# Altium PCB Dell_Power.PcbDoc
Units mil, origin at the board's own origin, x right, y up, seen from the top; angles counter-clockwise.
Board outline 2900 x 3225 mil, 2 copper layers (Top Layer, Bottom Layer); 31 components, 23 nets, 178 pads, 103 vias.
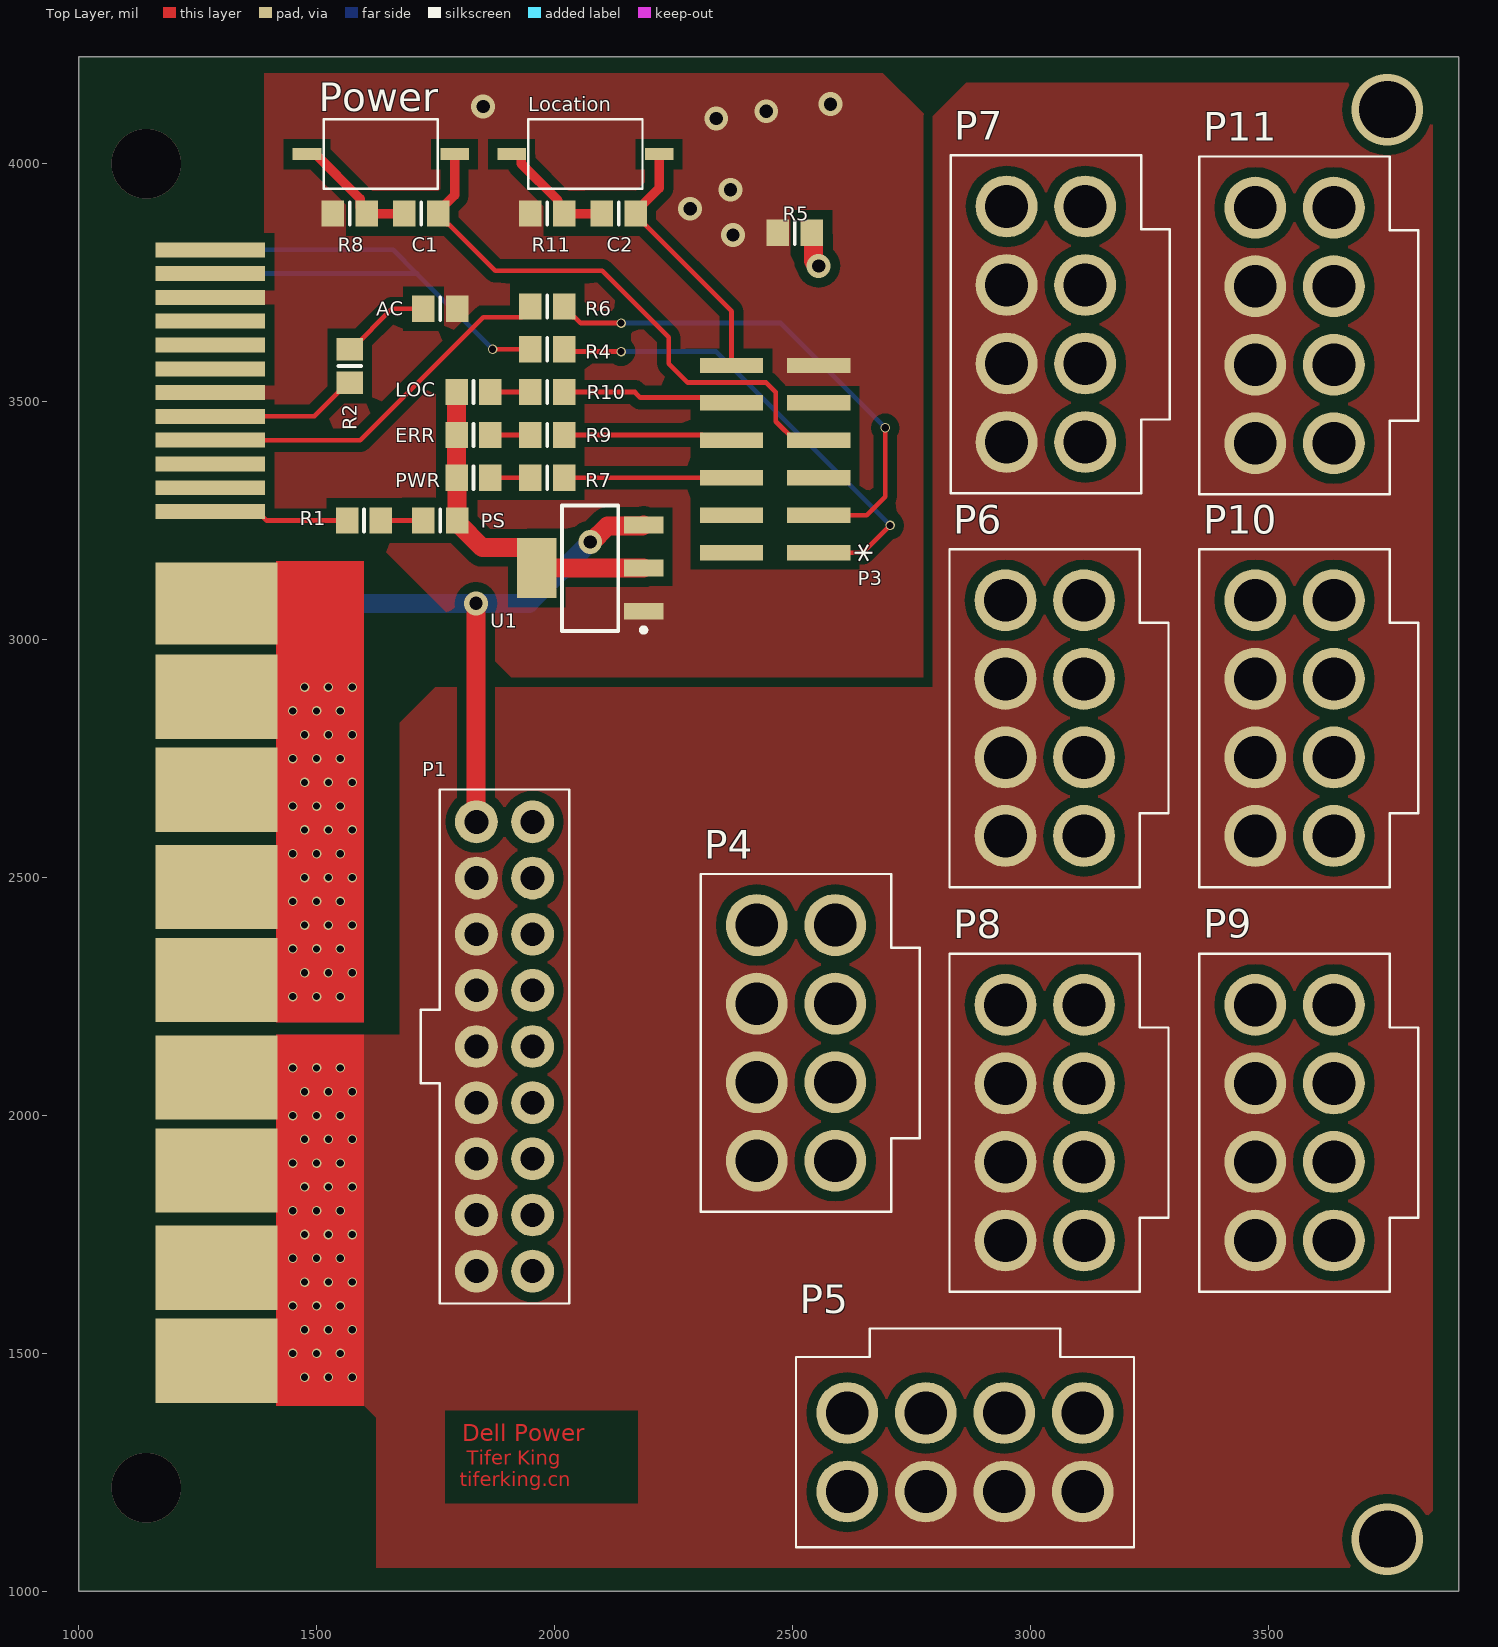
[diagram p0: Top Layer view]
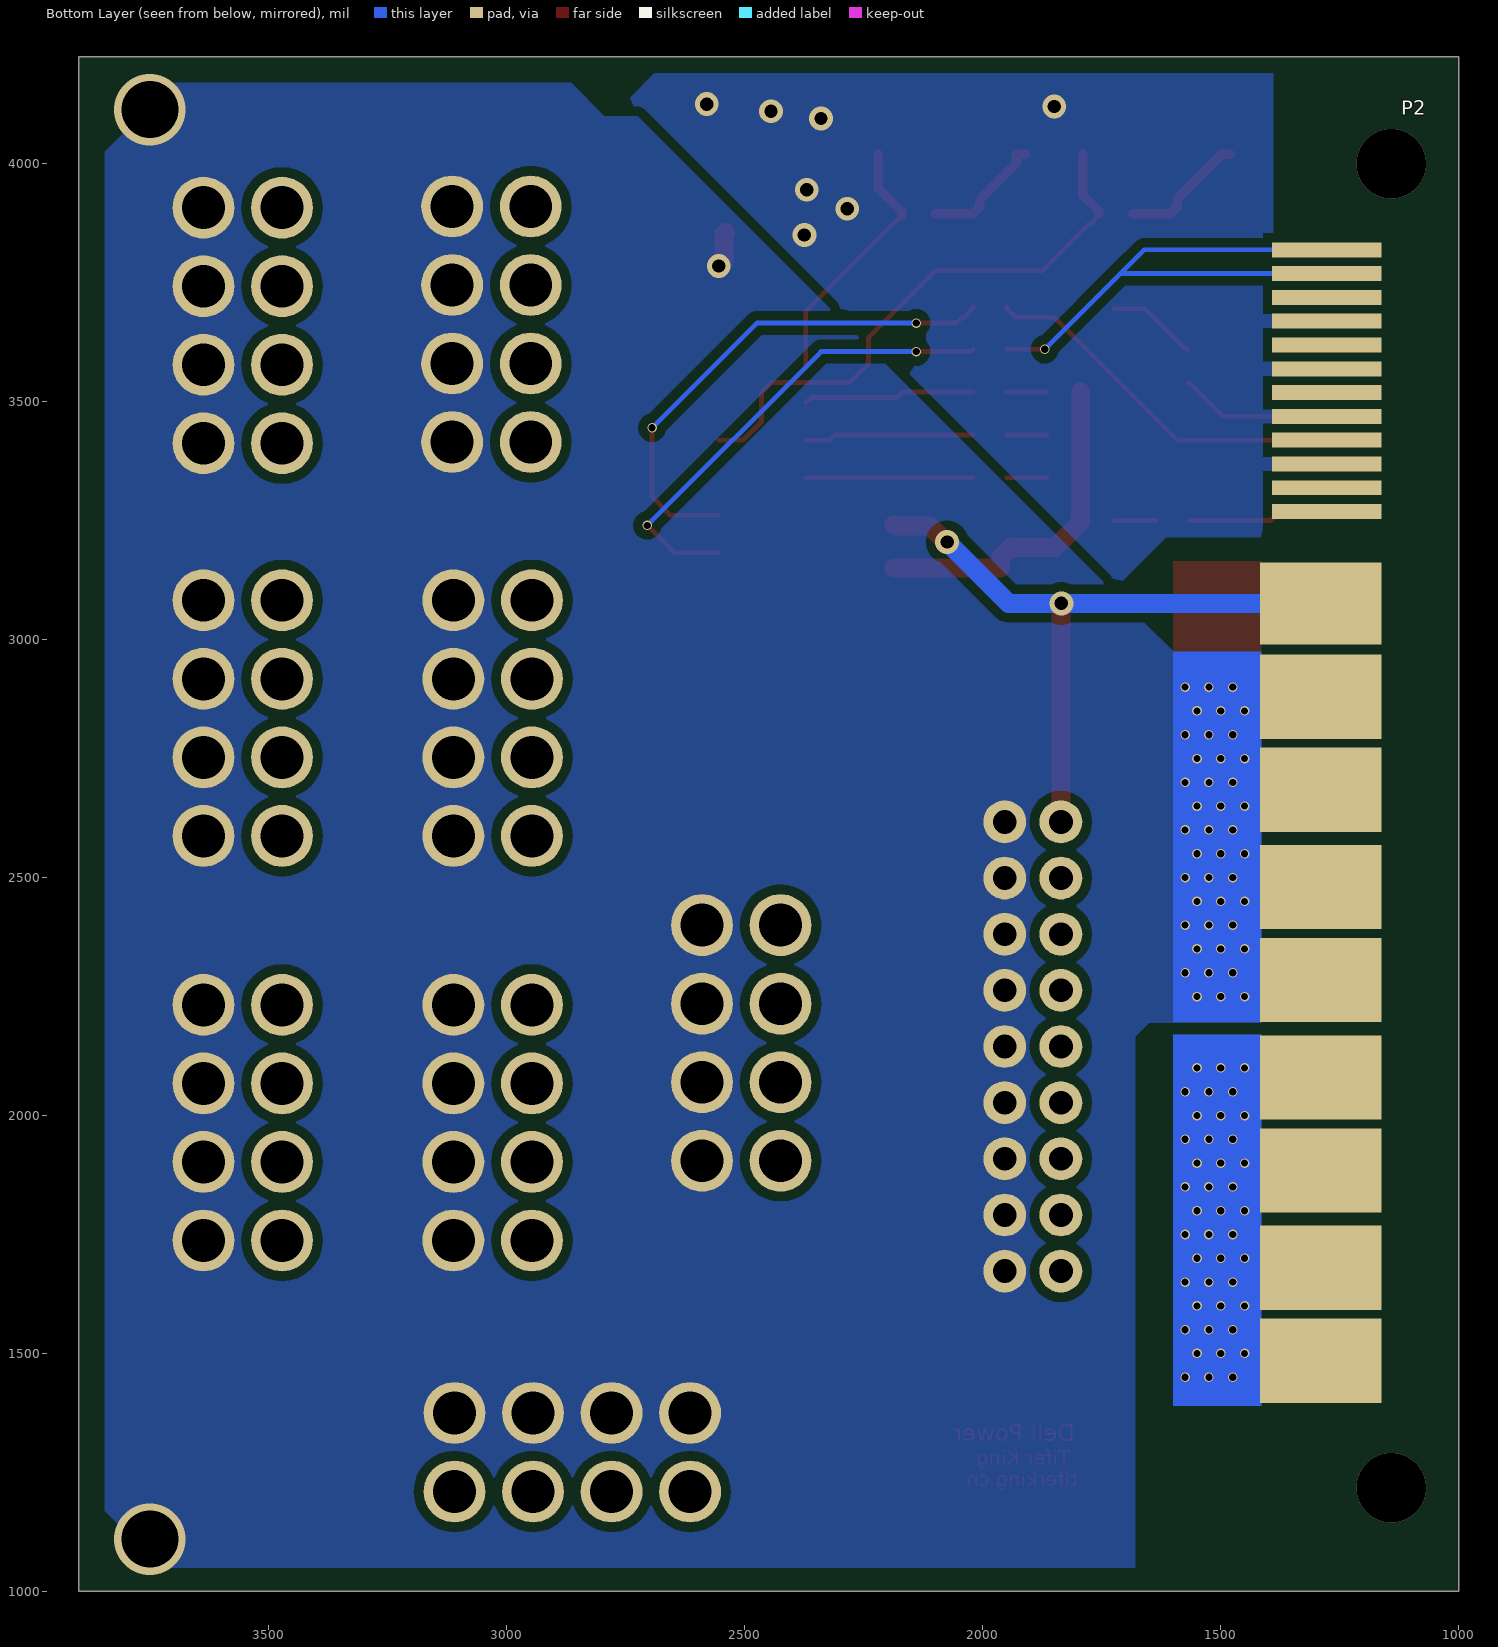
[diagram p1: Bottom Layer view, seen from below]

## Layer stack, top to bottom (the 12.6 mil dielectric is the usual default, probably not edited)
Top Solder: solder mask 0.4, Solder Resist, Dk 3.5
Top Layer: signal copper 1.4
Dielectric 1: dielectric 12.6, FR-4, Dk 4.8
Bottom Layer: signal copper 1.4
Bottom Solder: solder mask 0.4, Solder Resist, Dk 3.5

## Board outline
1000,1000 3900,1000 3900,4225 1000,4225

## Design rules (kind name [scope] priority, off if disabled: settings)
Clearance Polygon [InPolygon] p1: gap=20 ignorepadtopadclearanceinfootprint=FALSE except(0: Fill-Poly)
Clearance [All] p2: gap=10 ignorepadtopadclearanceinfootprint=FALSE except(0: Arc-Hole Track-Hole SMDPad-Hole THPad-Hole Via-Hole Fill-Hole Poly-Hole Region-Hole Text-Hole)
PlaneConnect [All] p1: planeconnectstyle=Relief reliefexpansion=20 reliefentries=4 reliefconductorwidth=30 reliefairgap=10
PolygonConnect [All] p1: connectstyle=Direct reliefconductorwidth=40 reliefentries=4 polygonreliefangle="45 Angle" airgapwidth=10
RoutingVias [All] p1: holewidth=28 width=50 viastyle="Through Hole" minholewidth=10 minwidth=10 maxholewidth=28 maxwidth=50
SolderMaskExpansion [All] p1: expansion=4 istentingtop=FALSE
Width [All] p1: maxlimit=100 minlimit=10 preferedwidth=40
29 further rules are at their usual default settings.

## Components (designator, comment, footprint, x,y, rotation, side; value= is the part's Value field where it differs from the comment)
AC "ACInput_OK" 6-0805_N 1760,3695 r0 top
C1 "10nF" 6-0805_N 1720,3895 r0 top
C2 "10nF" 6-0805_N 2135,3895 r180 top
ERR "LED_R" 6-0805_N 1830,3430 r0 top
LOC "LED_B" 6-0805_N 1830,3520 r0 top
Location "KEY" Key 2065,4020 r180 top
P1 "MX3.0" MX3.0 1895,2145 r90 top
P2 "Dell_Power" 10107844 1142,1218 r90 bottom
P3 "PWRCTL" PWRCTL 2463.5,3182.6 r90 top
P4 "5557-8" 5557-8 2507.5,2152.5 r270 top
P5 "5557-8" 5557-8 2862.5,1292.5 r0 top
P6 "5557-8" 5557-8 3030,2835 r270 top
P7 "5557-8" 5557-8 3032.5,3662.5 r270 top
P8 "5557-8" 5557-8 3030,1985 r270 top
P9 "5557-8" 5557-8 3555,1985 r270 top
P10 "5557-8" 5557-8 3555,2835 r270 top
P11 "5557-8" 5557-8 3555,3660 r270 top
Power "KEY" Key 1635,4020 r0 top
PS "PS PRESENT" 6-0805_N 1760,3250 r180 top
PWR "LED_G" 6-0805_N 1830,3340 r0 top
R1 "1K" 6-0805_N 1600,3250 r180 top
R2 "1K" 6-0805_N 1570,3575 r270 top
R4 "100R" 6-0805_N 1985,3610 r180 top
R5 "0R" 6-0805_N 2505,3855 r0 top
R6 "100R" 6-0805_N 1985,3700 r0 top
R7 "1K" 6-0805_N 1985,3340 r0 top
R8 "100R" 6-0805_N 1570,3895 r0 top
R9 "1K" 6-0805_N 1985,3430 r0 top
R10 "1K" 6-0805_N 1985,3520 r0 top
R11 "100R" 6-0805_N 1985,3895 r0 top
U1 "" SOT223-4L 2075,3150 r180 top

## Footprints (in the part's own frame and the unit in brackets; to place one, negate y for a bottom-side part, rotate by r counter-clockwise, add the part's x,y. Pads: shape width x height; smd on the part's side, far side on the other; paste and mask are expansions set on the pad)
6-0805_N [mm] "Chip Resistor, Body 2.0x1.2mm, IPC Medium Density"
  rect 1.2x1.4 smd: 1(-0.9,0) 2(0.9,0)
  silkscreen extent 0,-0.6 0,0.6, body extent -1.07,-0.7 1.07,0.7, height 0.7
5557-8 [mil]
  round 130 hole 90: 1(-247.5,-82.5) 2(-82.5,-82.5) 3(82.5,-82.5) 4(247.5,-82.5) 5(247.5,82.5) 6(82.5,82.5) 7(-82.5,82.5) 8(-247.5,82.5)
  silkscreen extent -355,-200 355,260
10107844 [mil]
  rect 177x256 smd far side paste+0 mask+0: P1-2(266.5,148) P3-4(462,148) P5-6(666.5,148) P7-8(862,148) P9-10(1066.5,148) P11-12(1262,148) P13-14(1466.5,148) P15-16(1662,148)
  rect 172.5x256 smd far side paste+0 mask+0: P17-18(1858,148)
  rect 172.5x256 smd paste+0 mask+0: P19-20(1858,148)
  rect 177x256 smd paste+0 mask+0: P21-22(1662,148) P23-24(1466.5,148) P25-26(1262,148) P27-28(1066.5,148) P29-30(862,148) P31-32(666.5,148) P33-34(462,148) P35-36(266.5,148)
  rect 31.5x230 smd far side paste+0 mask+0: S1(2051,135) S2(2101,135) S3(2151,135) S4(2201,135) S5(2251,135) S6(2301,135) S7(2351,135) S8(2401,135) S9(2451,135) S10(2501,135) S11(2551,135) S12(2601,135)
  rect 31.5x230 smd paste+0 mask+0: S13(2601,135) S14(2551,135) S15(2501,135) S16(2451,135) S17(2401,135) S18(2351,135) S19(2301,135) S20(2251,135) S21(2201,135) S22(2151,135) S23(2101,135) S24(2051,135)
Key [mil]
  rect 60x25 smd mask+0: 1(-155,0) 2(155,0)
  silkscreen extent -120,-73 120,73
MX3.0 [mil]
  round 90 hole 50: 1(-472,59) 2(-354,59) 3(-236,59) 4(-118,59) 5(0,59) 6(118,59) 7(236,59) 8(354,59) 9(472,59) 10(472,-59) 11(354,-59) 12(236,-59) 13(118,-59) 14(0,-59) 15(-118,-59) 16(-236,-59) 17(-354,-59) 18(-472,-59)
  silkscreen extent -540,-136 540,176
PWRCTL [mil]
  rect 32x133 smd mask+0: 1(0,-91.5) 2(78.7,-91.5) 3(157.4,-91.5) 4(236.1,-91.5) 5(314.8,-91.5) 6(393.5,-91.5) 7(393.5,91.5) 8(314.8,91.5) 9(236.1,91.5) 10(157.4,91.5) 11(78.7,91.5) 12(0,91.5)
SOT223-4L [mm] "SOT223, 4-Leads, Body 6.5x3.5mm, Pitch 2.3mm, Lead Span 7mm, IPC High Density"
  rect 2.1x0.9 smd: 1(-2.85,2.3) 2(-2.85,0) 3(-2.85,-2.3)
  rect 2.1x3.2 smd: 4(2.85,0)
  silkscreen extent -2.98,-3.35 1.5,3.42, body extent -1.85,-3.35 1.85,3.35, height 1.8

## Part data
AC ERR LOC PS PWR: library part LED0, "Typical INFRARED GaAs LED"
C1 C2: library part Cap, "Capacitor"
R1 R2 R4 R5 R6 R7 R8 R9 R10 R11: library part Res1, "Resistor"
U1: library part "Header 4", "Header, 4-Pin"

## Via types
v1: diameter 20, hole 15, Top Layer to Bottom Layer, 89 vias
v2: diameter 50, hole 28, Top Layer to Bottom Layer, 10 vias
v3: diameter 146, hole 146, Top Layer to Bottom Layer, 2 vias
v4: diameter 150, hole 120, Top Layer to Bottom Layer, 2 vias

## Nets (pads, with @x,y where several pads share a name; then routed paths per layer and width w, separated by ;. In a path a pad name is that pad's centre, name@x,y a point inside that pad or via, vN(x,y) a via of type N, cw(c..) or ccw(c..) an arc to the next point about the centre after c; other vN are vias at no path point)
+3.3: ERR.1 LOC.1 PS.1 PWR.1 U1.2 U1.4 | length 718.5
  Top Layer w40: LOC.1 ERR.1 PWR.1 1795,3339.57 1795,3250.43 PS.1 1795.43,3246.06 1848.5,3192.99 1941.46,3192.99 1962.79,3171.65 U1.4 U1.2
+12: P1.1 P1.2 P1.3 P1.4 P1.5 P1.6 P1.7 P1.8 P2.P1-2 P2.P3-4 P2.P5-6 P2.P7-8 P2.P29-30 P2.P31-32 P2.P33-34 P2.P35-36 P4.2 P4.3 P4.4 P5.2 P5.3 P5.4 P6.2 P6.3 P6.4 P7.2 P7.3 P7.4 P8.2 P8.3 P8.4 P9.2 P9.3 P9.4 P10.2 P10.3 P10.4 P11.2 P11.3 P11.4
  other v1: 1475,1450 1525,1450 1575,1450 1450,1500 1500,1500 1550,1500 1475,1550 1525,1550 1575,1550 1450,1600 1500,1600 1550,1600 1475,1650 1525,1650 1575,1650 1450,1700 1500,1700 1550,1700 1475,1750 1525,1750 1575,1750 1450,1800 1500,1800 1550,1800 1475,1850 1525,1850 1575,1850 1450,1900 1500,1900 1550,1900 1475,1950 1525,1950 1575,1950 1450,2000 1500,2000 1550,2000 1475,2050 1525,2050 1575,2050 1450,2100 1500,2100 1550,2100
+12Sub: P1.9 P2.P19-20 U1.3 | length 1426.2
  Top Layer w40: v2(1835,3076) 1835.5,3075.5 1835.5,2617.5 P1.9 ; v2(2075,3205) 2077.71,3205 2110.97,3238.27 2184.92,3238.27 U1.3
  Bottom Layer w40: P2.P19-20 v2(1835,3076) 1946,3076 v2(2075,3205) ; P1.9@1835,2618 P1.9
GND: P1.10 P1.11 P1.12 P1.13 P1.14 P1.15 P1.16 P1.17 P1.18 P2.P9-10 P2.P11-12 P2.P13-14 P2.P15-16 P2.P17-18 P2.P21-22 P2.P23-24 P2.P25-26 P2.P27-28 P4.5 P4.6 P4.7 P4.8 P5.5 P5.6 P5.7 P5.8 P6.5 P6.6 P6.7 P6.8 P7.5 P7.6 P7.7 P7.8 P8.5 P8.6 P8.7 P8.8 P9.5 P9.6 P9.7 P9.8 P10.5 P10.6 P10.7 P10.8 P11.5 P11.6 P11.7 P11.8 R5.2 | length 76
  Top Layer w40: R5.2 2544.06,3851.38 2544.06,3795.94 v2(2555,3785)
  other v1: 1450,2250 1500,2250 1550,2250 1475,2300 1525,2300 1575,2300 1450,2350 1500,2350 1550,2350 1475,2400 1525,2400 1575,2400 1450,2450 1500,2450 1550,2450 1475,2500 1525,2500 1575,2500 1450,2550 1500,2550 1550,2550 1475,2600 1525,2600 1575,2600 1450,2650 1500,2650 1550,2650 1475,2700 1525,2700 1575,2700 1450,2750 1500,2750 1550,2750 1475,2800 1525,2800 1575,2800 1450,2850 1500,2850 1550,2850 1475,2900 1525,2900 1575,2900
  other v4: 3750,1110 3750,4113.5
NetAC_1: AC.1 R2.1 | length 190.2
  Top Layer w10: R2.1@1570.43,3610 R2.1 1573.94,3610.43 1658.5,3695 AC.1
NetC1_1: C1.1 Power.1 R8.2 | length 266.3
  Top Layer w20: Power.1 1497.5,4020 1591.81,3925.69 1591.81,3908.62 R8.2 C1.1
NetC1_2: C1.2 P3.4 Power.2 | length 1206.9
  Top Layer w10: C1.2 1755.43,3891.06 1774.06,3872.44 1777.99,3872.44 1875.43,3775 2100,3775 2240,3635 2240,3580 2280,3540 2445,3540 2465,3520 2465,3458.2 2504.5,3418.7 P3.4
  Top Layer w20: C1.2 1755.43,3898.94 1790,3933.5 Power.2
NetC2_1: C2.1 Location.1 P3.7 | length 547.9
  Top Layer w10: C2.1@2170.43,3891.06 2372,3689.5 P3.7
  Top Layer w20: C2.1@2170.43,3891.06 C2.1 2170.43,3898.94 2220,3948.5 Location.1
NetC2_2: C2.2 Location.2 R11.2 | length 260.1
  Top Layer w20: Location.2 1927.5,4020 1930,4017.5 1930,4000 2006.81,3923.19 2006.81,3908.62 R11.2 C2.2
NetERR_2: ERR.2 R9.1 | length 84.1
  Top Layer w10: ERR.2 R9.1
NetLOC_2: LOC.2 R10.1 | length 84.1
  Top Layer w10: LOC.2 R10.1
NetP2_S1: P2.S1 R1.2 | length 295.4
  Top Layer w10: P2.S1 1376.25,3269 1395.25,3250 R1.2
NetP2_S4: P2.S4 R6.1 | length 791.3
  Top Layer w10: P2.S4 1591.83,3419 1850.27,3677.44 1930.94,3677.44 1949.57,3696.06 R6.1
NetP2_S5: P2.S5 R2.2 | length 322.2
  Top Layer w10: P2.S5 1495.5,3469 1566.06,3539.57 R2.2
NetP2_S13: P2.S13 P2.S14 R4.2 | length 1193.1
  Top Layer w10: v1(1870,3610) R4.2
  Bottom Layer w10: P2.S14 1711,3769 ; P2.S13 1661,3819 1711,3769 ; v1(1870,3610) 1711,3769
NetP3_1: P3.1 R4.1 | length 1011.6
  Top Layer w10: R4.1 2025.43,3605 v1(2140,3605) ; P3.1 2647.6,3182.6 v1(2705,3240)
  Bottom Layer w10: v1(2140,3605) 2340,3605 v1(2705,3240)
NetP3_2: P3.2 R6.2 | length 1083.5
  Top Layer w10: R6.2 2020.43,3696.06 2039.06,3677.44 2042.99,3677.44 2055.43,3665 v1(2140,3665) ; P3.2 2656.3,3261.3 2695,3300 v1(2695,3445)
  Bottom Layer w10: v1(2140,3665) 2475,3665 v1(2695,3445)
NetP3_8: P3.8 R10.2 | length 360.9
  Top Layer w10: R10.2 2168.98,3520 2180.58,3508.4 2361,3508.4 P3.8
NetP3_9: P3.9 R9.2 | length 356.2
  Top Layer w10: R9.2 2310.2,3430 2321.5,3418.7 P3.9
NetP3_10: P3.10 R7.2 | length 351.6
  Top Layer w10: R7.2 P3.10
NetPS_2: PS.2 R1.1 | length 89.1
  Top Layer w10: R1.1 PS.2
NetPWR_2: PWR.2 R7.1 | length 84.1
  Top Layer w10: PWR.2 R7.1
SGND: AC.2 P2.S6 P2.S10 P2.S16 P2.S18 P2.S20 P2.S22 P3.6 R5.1 R8.1 R11.1 U1.1
  other v2: 2375,3850 2285,3905 2370,3945 2340,4095 2445,4110 1850,4120 2580,4125
pads on no net: P2.S2 P2.S3 P2.S7 P2.S8 P2.S9 P2.S11 P2.S12 P2.S15 P2.S17 P2.S19 P2.S21 P2.S23 P2.S24 P3.3 P3.5 P3.11 P3.12 P4.1 P5.1 P6.1 P7.1 P8.1 P9.1 P10.1 P11.1
copper on no net:
  other v3: 1142,1218 1142,4000

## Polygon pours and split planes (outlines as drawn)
SGND on Top Layer "SGND_L01_P001" (solid, pour order 1): 1390,3215 1615,3215 1930,2900 2795,2900 2795,4085 2690,4190 1390,4190
+12 on Top Layer "+12_L01_P000" (solid, pour order 0): 1600,1390 1625,1365 1625,1050 3725,1050 3845,1170 3845,4170 2865,4170 2795,4100 2795,2900 1750,2900 1675,2825 1675,2170 1600,2170
SGND on Bottom Layer "SGND_L02_P003" (solid, pour order 3): 1390,3215 1615,3215 1930,2900 2795,2900 2795,4085 2690,4190 1390,4190
GND on Bottom Layer "GND_L02_P002" (solid, pour order 2): 1600,2195 1650,2195 1680,2165 1680,1050 3725,1050 3845,1170 3845,4025 3700,4170 2865,4170 2795,4100 2725,4100 1600,2975
no net on Top Solder (solid): 1780,1370 1780,1195 2165,1195 2165,1370

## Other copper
Top Layer:
  region net GND: 1600,3165 1415,3165 1415,2195 1600,2195
  rectangle net +12: 1415,1390 1600,2170
  pour cut-out: 1770,1380 2175,1380 2175,1185 1770,1185
  text "Dell Power" at 1806,1316 h35
  text "Tifer King" at 1816,1266 h30
  text "tiferking.cn" at 1801,1221 h30
Bottom Layer:
  region net GND: 1600,2975 1415,2975 1415,2195 1600,2195
  rectangle net +12: 1415,1390 1600,2170

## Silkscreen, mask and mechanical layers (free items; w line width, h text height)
Mechanical 1:
  lines w5: 1000,1050 ccw(c1050,1050) 1050,1000 3850,1000 ccw(c3850,1050) 3900,1050 3900,4173.5 ccw(c3850,4173.5) 3850,4223.5 1050,4223.5 ccw(c1050,4173.5) 1000,4173.5 1000,4003.5 1000,3915.5 1040,3875.5 1092,3875.5 cw(c1092,3825.5) 1142,3825.5 1142,1398 cw(c1092,1398) 1092,1348 1040,1348 1000,1308 1000,1220 1000,1050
